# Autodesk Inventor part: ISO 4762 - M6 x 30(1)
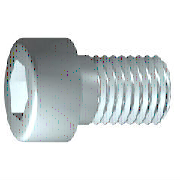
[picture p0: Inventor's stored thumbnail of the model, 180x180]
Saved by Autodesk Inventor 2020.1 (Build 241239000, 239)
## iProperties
Created: 2019-01
Part Number: ISO 4762 - M6 x 30(1)
Material: Edelstahl, 440C
Description: Innensechskantschraube
Document SubType Name: Modeling
Standard: ISO 4762
Designer: lutzd
Standard Revision: Fourth edition 2004-03-01
Standards Organization: ISO
Language: de-DE
Size Designation: M6 x 30
Categories: <MemberInstance><Categories><Category DisplayName="Verbindungselemente" InternalName="e4da775c-781d-43d5-af7c-5136215cf5a6" Mnemonic="FSTN"><Category DisplayNam
Mass: 9.56928 g
Surface Area: 9.52595 cm^2
Volume: 1.23475 cm^3
Density: 7.75 g/cm^3
Appearance: Halbpoliert
IsCustomPart: 0
Author: lutzd
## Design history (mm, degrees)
body "Solid1"
sketch "Skizze1"
  geometry: L1 (-1.333, 0)-(30, 0); L2 (30, 0)-(30, 3); L3 (30, 3)-(2.5, 3); L4 (2.5, 3)-(1.886, 3); L5 (1.886, 3)-(0, 3); L6 (0, 3)-(0, 5); L7 (0, 5)-(-6, 5); L8 (-6, 5)-(-6, 2.887); L9 (-6, 2.887)-(-3, 2.887); L10 (-3, 2.887)-(-1.333, 0); L11 (-13.2, 0)-(37.2, 0) reference; L12 (0, -1)-(0, 6) reference; L13 (2.5, 3)-(0, 3)
  constraints: 22 end point, 6 parallel, 2 collinear, 2 perpendicular, 1 horizontal, 1 point on line
  dimensions: "d1" = 27.5 distance from line of L3.end L2 (= GEL); "d2" = 0.61355 distance of L4.end L3.end (computed from GAL); "d3" = 6 distance between parallel lines of L8 L6 (= KOH); "d4" = 3 distance of L8.end L9.end (= INTI); "d5" = 60 deg angle of L10 L1; "d6" = 6 diameter of L3 L1 (= GD); "d7" = 6 diameter of L5 L1 (= BDM); "d8" = 5.7735 diameter of L9 L1 (= 1.1547 x SW); "d9" = 10 diameter of L7 L1 (= KOD); "d26" = 30 distance between parallel lines of L12 L2 (= NLG)
revolve "Körper" stored, may be unused: angle "d10" = 90 deg
sketch "Skizze2"
  geometry: L1 (0, -7)-(0, 7) reference; L2 (-7, 0)-(7, 0) reference; L3 (2.887, 0)-(1.443, -2.5); L4 (1.443, -2.5)-(-1.443, -2.5); L5 (-1.443, -2.5)-(-2.887, 0); L6 (-2.887, 0)-(-1.443, 2.5); L7 (-1.443, 2.5)-(1.443, 2.5); L8 (1.443, 2.5)-(2.887, 0); 2 further points
  constraints: 12 end point, 1 coincident, 1 horizontal alignment, 1 point on line, 12 other
extrude "Loch" join sketch "Skizze2" stored distance "d11" = 10; taper "d12" = 0 deg
workplane "Work Plane1"
fillet "Fillet2" dims "d30" = 0.1 (= R)
fillet "Rundung1" dims "d17" = 0.6 (= RR)
feature "Gewinde" dims "d13" = 27.5 (= GEL), "d14" = 0
chamfer "Fase1" distance "d15" = 0.61345 (= -0.5 x SPD + 0.5 x GD); stored, may be unused: second distance "d16" = 0.61345 (= GUL), angle "d27" = 45 deg
other parameters: "GD" = 6 [user parameter; used in 2 equation terms], "NLG" = 30 [user parameter; used in 1 equation term], "GEL" = 27.5 [user parameter; used in 2 equation terms], "KOD" = 10 [user parameter; used in 1 equation term], "KOH" = 6 [user parameter; used in 1 equation term], "INTI" = 3 [user parameter; used in 1 equation term], "GAL" = 0.61345 (= 0.61345 x PTC) [user parameter; used in 1 equation term], "GUL" = 0.61345 (= 0.61345 x PTC) [user parameter; used in 1 equation term], "BDM" = 6 (= NND) [user parameter; used in 1 equation term], "SW" = 5 [user parameter; used in 2 equation terms], "RR" = 0.6 [user parameter; used in 1 equation term], "SPD" = 4.7731 (= NND - 1.2269 x PTC) [user parameter; used in 1 equation term], "d19" = 0, "d28" = 0, "d29" = 0, "R" = 0.1 [user parameter; used in 1 equation term], "TOA" = 30 deg [user parameter], "GD1" = 4.7731 (= THREADDIA - 1.2269 x PTC) [user parameter], "THREADDIA" = 6 [user parameter; used in 1 equation term], "FAWI" = 45 deg [user parameter], "PTC" = 1 [user parameter; used in 5 equation terms], "NND" = 6 [user parameter; used in 2 equation terms], "E0" = 5.775 (= 1.155 x SW) [user parameter]
